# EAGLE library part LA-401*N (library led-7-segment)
Single Digit LED Numeric Display (cathode common) Source: ROHM .. la-1401dn.pdf
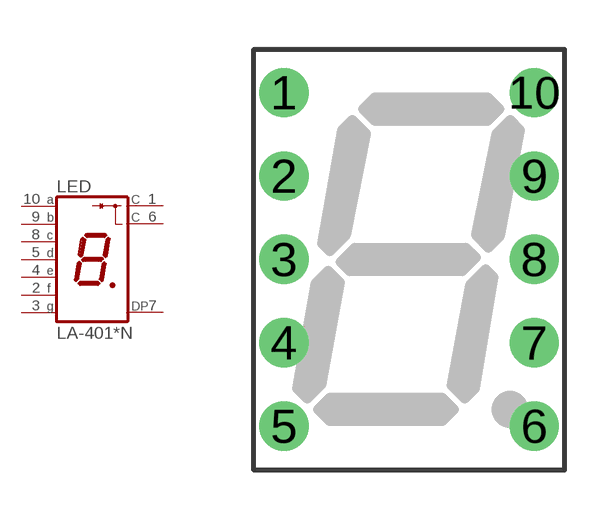
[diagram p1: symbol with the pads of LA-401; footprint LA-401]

Designator prefix LED

## LA-401AN (OC_FARNELL: unknown; OC_NEWARK: unknown), LA-401BN (OC_FARNELL: unknown; OC_NEWARK: unknown), LA-401EN (OC_FARNELL: unknown; OC_NEWARK: unknown), LA-401MN (OC_FARNELL: unknown; OC_NEWARK: unknown), LA-401VN (OC_FARNELL: unknown; OC_NEWARK: unknown), LA-401XN (OC_FARNELL: unknown; OC_NEWARK: unknown)  [LA-401]
1  C  pas
2  F  pas
3  G  pas
4  E  pas
5  D  pas
6  C  pas
7  DP  pas
8  C  pas
9  B  pas
10  A  pas

## Footprint LA-401 (pad centres in mm)
Single Digit LED Numeric Display 10.16 mm Source: ROHM .. la-401dn.pdf
drill 0.9 pad 1.5 round: 1 -3.81,5.08; 2 -3.81,2.54; 3 -3.81,0; 4 -3.81,-2.54; 5 -3.81,-5.08; 6 3.81,-5.08; 7 3.81,-2.54; 8 3.81,0; 9 3.81,2.54; 10 3.81,5.08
